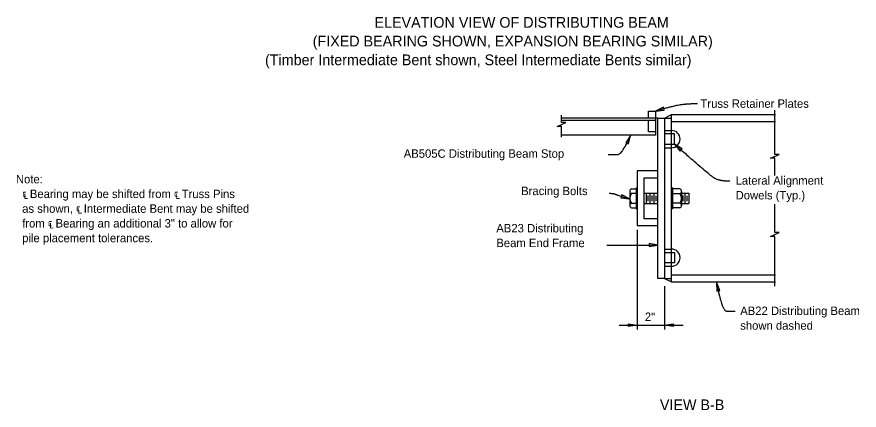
# Model space of a CAD drawing. Extents: x 0.1 to 14.7, y 0.1 to 9.6.
# Drawn here: x 1.07 to 8.62, y 0.19 to 3.72 of the extents above; entities that cross this region are included whole.
import ezdxf

# ---------------------------------------------------------------- set-up
doc = ezdxf.new("R2010")
doc.units = 0
for name, color, linetype in [('Dimension', 7, 'Continuous'), ('SteelMisc', 7, 'Continuous'), ('SteelMisc_h', 7, 'Continuous'), ('Symbols', 7, 'Continuous'), ('TextStructures', 7, 'Continuous')]:
    doc.layers.add(name, color=color, linetype=linetype)

msp = doc.modelspace()

# ---------------------------------------------------------------- linework, layer by layer
at = {"layer": 'Dimension'}
for p, q in [((6.6321, 1.8088), (6.6321, 0.9152)), ((6.3599, 1.6712), (6.8158, 1.6712)), ((6.8771, 1.3038), (6.8771, 0.9152)), ((6.4689, 0.953), (7.0444, 0.953))]:
    msp.add_line(p, q, dxfattribs=at)
for points in [[(6.7954, 2.8731), (6.8742, 2.8811), (6.8672, 2.9066)], [(6.5729, 2.6546), (6.5286, 2.5889), (6.5527, 2.578)], [(6.9667, 2.5751), (7.0163, 2.5134), (7.0338, 2.5332)], [(6.5638, 2.0849), (6.4932, 2.1208), (6.4853, 2.0956)], [(6.8158, 1.6712), (6.7377, 1.6845), (6.7377, 1.658)], [(7.3421, 1.3382), (7.346, 1.2591), (7.3719, 1.2648)], [(6.554, 0.9662), (6.6321, 0.953), (6.554, 0.9398)], [(6.9552, 0.9398), (6.8771, 0.953), (6.9552, 0.9662)]]:
    msp.add_lwpolyline(points, close=True, dxfattribs=at)
for points in [[(7.1712, 2.937), (7.097, 2.937), (6.9772, 2.9232), (6.7954, 2.8731)], [(6.371, 2.4843), (6.4217, 2.4843), (6.4957, 2.4843), (6.5729, 2.6546)], [(7.4636, 2.2432), (7.3671, 2.2432), (7.2735, 2.3028), (6.9667, 2.5751)], [(6.3794, 2.1355), (6.4152, 2.1355), (6.4626, 2.1165), (6.5638, 2.0849)], [(7.5108, 1.0768), (7.4539, 1.0768), (7.4159, 1.0768), (7.3738, 1.1949), (7.3421, 1.3382)]]:
    msp.add_open_spline(points, degree=2, dxfattribs=at)
at = {"layer": 'SteelMisc'}
for p, q in [((6.8158, 2.8104), (5.9537, 2.8104)), ((6.8771, 2.8103), (6.9397, 2.8415)), ((6.8771, 2.8103), (6.9397, 2.8103)), ((6.9397, 1.3415), (6.9397, 2.8415)), ((6.9397, 2.8415), (7.8709, 2.8415)), ((6.9397, 2.7802), (7.8709, 2.7802)), ((6.7954, 2.6559), (5.9537, 2.6559)), ((6.8771, 2.6982), (6.9397, 2.6982)), ((6.9667, 2.667), (6.8771, 2.667)), ((6.9667, 2.5751), (6.9667, 2.667)), ((6.8771, 2.5751), (6.9667, 2.5751)), ((6.8771, 2.5439), (6.9397, 2.5439)), ((6.565, 2.1528), (6.565, 2.0267)), ((6.5807, 2.1754), (6.6236, 2.1754)), ((6.6236, 2.1326), (6.5807, 2.1326)), ((6.6236, 2.1835), (6.6321, 2.1835)), ((6.6236, 2.1835), (6.6236, 1.996)), ((6.6934, 2.1366), (6.8158, 2.1366)), ((6.7107, 2.1366), (6.7107, 2.043)), ((6.7457, 2.1366), (6.7457, 2.043)), ((6.7808, 2.1366), (6.7808, 2.043)), ((6.9482, 2.1835), (6.9397, 2.1835)), ((6.9482, 2.1835), (6.9482, 1.996)), ((7.0147, 2.1754), (6.9482, 2.1754)), ((6.9482, 2.1326), (7.0147, 2.1326)), ((7.0304, 2.1528), (7.0304, 2.0267)), ((7.0304, 2.1366), (7.0938, 2.1366)), ((7.0588, 2.1366), (7.0588, 2.043)), ((7.0938, 2.1366), (7.0938, 2.043)), ((6.5807, 2.0469), (6.6236, 2.0469)), ((6.6934, 2.043), (6.8158, 2.043)), ((6.7282, 2.1144), (6.7282, 2.0651)), ((6.7632, 2.1144), (6.7632, 2.0651)), ((6.7983, 2.1139), (6.7983, 2.0651)), ((7.0147, 2.0469), (6.9482, 2.0469)), ((7.0304, 2.043), (7.0938, 2.043)), ((7.0412, 2.1144), (7.0412, 2.0651)), ((7.0763, 2.1139), (7.0763, 2.0651)), ((6.5807, 2.0041), (6.6236, 2.0041)), ((6.6236, 1.996), (6.6321, 1.996)), ((6.9482, 1.996), (6.9397, 1.996)), ((7.0147, 2.0041), (6.9482, 2.0041)), ((6.8771, 1.6356), (6.9397, 1.6356)), ((6.8771, 1.6044), (6.9667, 1.6044)), ((6.9667, 1.6044), (6.9667, 1.5125)), ((6.9667, 1.5125), (6.8771, 1.5125)), ((6.9667, 1.5125), (6.9397, 1.5125)), ((6.8771, 1.4813), (6.9397, 1.4813)), ((6.8771, 1.3728), (6.9397, 1.3728)), ((6.8771, 1.3728), (6.9397, 1.3415)), ((6.9397, 1.4029), (7.8709, 1.4029)), ((6.9397, 1.3415), (7.8709, 1.3415))]:
    msp.add_line(p, q, dxfattribs=at)
msp.add_lwpolyline([(6.7341, 2.8104), (6.7341, 2.8731), (6.7954, 2.8731), (6.7954, 2.6559)], dxfattribs=at)
for points in [[(6.8771, 1.3728), (6.8158, 1.3728), (6.8158, 2.8104), (6.8771, 2.8104)], [(6.8158, 2.3367), (6.6321, 2.3367), (6.6321, 1.8466), (6.8158, 1.8466), (6.8158, 1.9079), (6.6934, 1.9079), (6.6934, 2.2754), (6.8158, 2.2754)]]:
    msp.add_lwpolyline(points, close=True, dxfattribs=at)
for centre, radius, start, end in [((6.9396, 2.6211), 0.0771, 270.02786, 89.97214), ((6.5874, 2.154), 0.0224, 107.25576, 183.01536), ((6.5874, 2.154), 0.0224, 183.01536, 252.74424), ((6.6311, 2.0898), 0.0661, 139.64006, 220.35994), ((7.0081, 2.154), 0.0224, 356.98464, 72.74424), ((7.0081, 2.154), 0.0224, 287.25576, 356.98464), ((6.9643, 2.0898), 0.0661, 319.64006, 40.35994), ((6.5874, 2.0255), 0.0224, 107.25576, 176.98464), ((7.0081, 2.0255), 0.0224, 3.01536, 72.74424), ((6.5874, 2.0255), 0.0224, 176.98464, 252.74424), ((7.0081, 2.0255), 0.0224, 287.25576, 3.01536), ((6.9396, 1.5585), 0.0771, 270.02786, 89.97214)]:
    msp.add_arc(centre, radius, start, end, dxfattribs=at)
at = {"layer": 'SteelMisc_h'}
for p, q in [((6.7954, 2.7893), (5.9537, 2.7893)), ((6.7341, 2.6856), (6.7341, 2.7893))]:
    msp.add_line(p, q, dxfattribs=at)
msp.add_lwpolyline([(6.7954, 2.6856), (6.7341, 2.6856)], dxfattribs=at)
at = {"layer": 'Symbols'}
for points in [[(7.8646, 2.2943), (7.8646, 2.4493), (7.8259, 2.4493), (7.9034, 2.483), (7.8646, 2.483), (7.8646, 2.8793)], [(5.9537, 2.6396), (5.9537, 2.7352), (5.915, 2.7352), (5.9925, 2.769), (5.9537, 2.769), (5.9537, 2.8346)], [(7.8646, 1.3026), (7.8646, 1.7495), (7.8259, 1.7495), (7.9034, 1.7832), (7.8646, 1.7832), (7.8646, 2.039)]]:
    msp.add_lwpolyline(points, dxfattribs=at)

# ---------------------------------------------------------------- texts
at = {"layer": 'Dimension'}
msp.add_text('2"', height=0.0756, dxfattribs=at).set_placement((6.7004, 0.9908))
at = {"layer": 'TextStructures'}
for s, height, p in [('ELEVATION VIEW OF DISTRIBUTING BEAM', 0.096, (4.2759, 3.6199)), ('(FIXED BEARING SHOWN, EXPANSION BEARING SIMILAR)', 0.096, (3.7216, 3.4519)), ('(Timber Intermediate Bent shown, Steel Intermediate Bents similar) ', 0.096, (3.2942, 3.2839)), ('Truss Retainer Plates ', 0.0756, (7.1991, 2.902)), ('AB505C Distributing Beam Stop', 0.0756, (4.5379, 2.4538)), ('Note:', 0.0756, (1.0603, 2.2245)), ('Lateral Alignment ', 0.0756, (7.5142, 2.2124)), ('Bracing Bolts', 0.0756, (5.591, 2.1189)), ('  ℄ Bearing may be shifted from ℄ Truss Pins ', 0.0756, (1.0603, 2.0925)), ('Dowels (Typ.)', 0.0756, (7.5142, 2.0804)), ('  as shown, ℄ Intermediate Bent may be shifted', 0.0756, (1.0603, 1.9605)), ('  from ℄ Bearing an additional 3" to allow for ', 0.0756, (1.0603, 1.8285)), ('AB23 Distributing ', 0.0756, (5.3684, 1.7847)), ('  pile placement tolerances.', 0.0756, (1.0603, 1.6965)), ('Beam End Frame', 0.0756, (5.3684, 1.6527)), ('AB22 Distributing Beam ', 0.0756, (7.5555, 1.0442)), ('shown dashed', 0.0756, (7.5555, 0.9122)), ('VIEW B-B', 0.096, (6.8353, 0.1912))]:
    msp.add_text(s, height=height, dxfattribs=at).set_placement(p)

doc.saveas('drawing.dxf')
